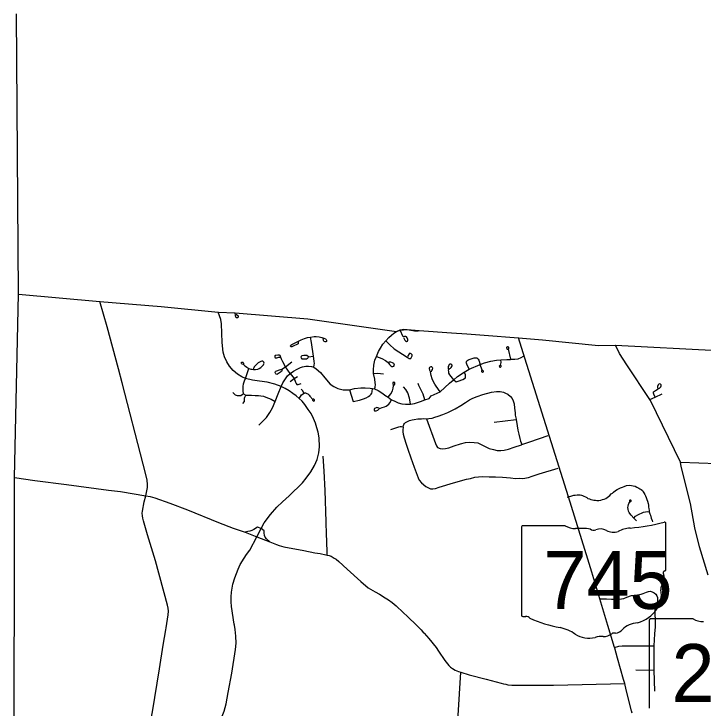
# Model space of a CAD drawing. Extents: x 1755200 to 1902939, y 644115 to 788070.
# Drawn here: x 1781021 to 1797614, y 771361 to 788070 of the extents above; entities that cross this region are included whole.
import ezdxf

# ---------------------------------------------------------------- set-up
doc = ezdxf.new("R2010")
doc.units = 0
for name, color, linetype in [('GM_X_Adjacent_County', 7, 'Continuous'), ('GM_X_City_Street', 7, 'Continuous'), ('GM_X_County', 7, 'Continuous'), ('GM_X_County_Road', 7, 'Continuous'), ('GM_X_State_Route', 7, 'Continuous'), ('GM_X_State_Shield', 7, 'Continuous')]:
    doc.layers.add(name, color=color, linetype=linetype)

msp = doc.modelspace()

# ---------------------------------------------------------------- linework, layer by layer
at = {"layer": 'GM_X_Adjacent_County'}
msp.add_line((1781136, 781321), (1781087, 788070), dxfattribs=at)
at = {"layer": 'GM_X_City_Street'}
for points in [[(1784685, 773296), (1784735, 773603), (1784745, 773698), (1784736, 773770), (1784721, 773835), (1784428, 774903), (1784235, 775534), (1784138, 775865), (1784125, 775929), (1784115, 775990), (1784111, 776055), (1784114, 776105), (1784158, 776324), (1784196, 776473), (1784235, 776672), (1784238, 776744), (1784231, 776844), (1784215, 776918), (1784131, 777234), (1783629, 779189), (1783538, 779530), (1783263, 780534), (1783093, 781151)], [(1786330, 773355), (1786325, 773382), (1786259, 773807), (1786250, 773917), (1786254, 774036), (1786263, 774150), (1786294, 774341), (1786338, 774493), (1786420, 774704), (1786472, 774820), (1786567, 774969), (1786624, 775055), (1786702, 775162), (1786871, 775480), (1786971, 775687), (1787044, 775818), (1787200, 776018), (1787355, 776199), (1787487, 776323), (1787646, 776467), (1787967, 776780), (1788061, 776896), (1788172, 777044), (1788262, 777203), (1788323, 777346), (1788361, 777509), (1788375, 777651), (1788370, 777868), (1788349, 778002), (1788313, 778109), (1788283, 778223), (1788238, 778334), (1788176, 778450), (1788109, 778552), (1788029, 778665), (1787959, 778747), (1787890, 778815), (1787816, 778881), (1787737, 778934), (1787651, 778995), (1787548, 779052), (1787457, 779100), (1787307, 779157), (1787116, 779208), (1786932, 779232), (1786764, 779254), (1786595, 779297), (1786510, 779336), (1786405, 779397), (1786303, 779486), (1786215, 779591), (1786147, 779695), (1786093, 779813), (1786060, 779930), (1786037, 780162), (1786019, 780607), (1786002, 780713), (1785941, 780892)], [(1786370, 780841), (1786422, 780806), (1786421, 780769), (1786415, 780760), (1786404, 780754), (1786381, 780755), (1786367, 780773), (1786357, 780809), (1786346, 780876)], [(1789704, 779043), (1789715, 779089), (1789724, 779146), (1789722, 779192), (1789709, 779277), (1789682, 779417), (1789680, 779501), (1789687, 779615), (1789709, 779735), (1789747, 779826), (1789795, 779948), (1789843, 780028), (1789906, 780123), (1789973, 780198), (1790046, 780282), (1790110, 780341), (1790166, 780385), (1790229, 780426), (1790323, 780455), (1790403, 780463), (1790491, 780471), (1790665, 780443), (1790696, 780441), (1790728, 780441), (1790750, 780442), (1790776, 780453)], [(1787867, 780179), (1787862, 780147), (1787861, 780131), (1787729, 780062), (1787712, 780054), (1787701, 780053), (1787689, 780060), (1787680, 780074), (1787686, 780094), (1787709, 780109), (1787748, 780129), (1787941, 780223), (1788020, 780258), (1788093, 780280), (1788164, 780289), (1788254, 780303), (1788299, 780305), (1788369, 780298), (1788433, 780283), (1788485, 780266), (1788520, 780252), (1788540, 780230), (1788546, 780218), (1788551, 780205), (1788546, 780189), (1788545, 780184), (1788532, 780177), (1788521, 780174), (1788515, 780174), (1788488, 780185), (1788482, 780196), (1788475, 780211), (1788472, 780225), (1788470, 780242), (1788474, 780262)], [(1790400, 780283), (1790418, 780247), (1790434, 780217), (1790446, 780201), (1790471, 780188), (1790486, 780189), (1790493, 780196), (1790505, 780209), (1790508, 780220), (1790508, 780235), (1790500, 780254), (1790491, 780277), (1790475, 780298), (1790458, 780306), (1790428, 780307), (1790395, 780294), (1790323, 780455)], [(1788243, 779570), (1788252, 779625), (1788258, 779657), (1788253, 779702), (1788244, 779774), (1788235, 779829), (1788185, 780159), (1788164, 780289)], [(1789973, 780198), (1790068, 780107), (1790178, 780010), (1790488, 779809), (1790541, 779778), (1790574, 779776), (1790593, 779804), (1790609, 779841), (1790609, 779864), (1790587, 779889), (1790556, 779901), (1790539, 779887), (1790496, 779823)], [(1792988, 779756), (1792931, 779997), (1792938, 780010), (1792939, 780025), (1792937, 780041), (1792932, 780051), (1792921, 780055), (1792906, 780056), (1792894, 780052), (1792888, 780049), (1792884, 780043), (1792882, 780030), (1792886, 780020), (1792890, 780010), (1792899, 780001), (1792909, 779998), (1792929, 779997)], [(1787676, 779417), (1787558, 779577), (1787492, 779693), (1787467, 779759), (1787440, 779825), (1787428, 779849), (1787417, 779859), (1787379, 779858), (1787325, 779851), (1787314, 779847), (1787304, 779836), (1787302, 779814), (1787311, 779794), (1787328, 779788), (1787348, 779789), (1787374, 779798), (1787396, 779806), (1787437, 779808)], [(1788115, 779819), (1788071, 779851), (1788053, 779851), (1787998, 779847), (1787956, 779838), (1787936, 779824), (1787933, 779811), (1787937, 779798), (1787942, 779777), (1787950, 779770), (1787962, 779766), (1787988, 779765), (1788076, 779769), (1788085, 779773), (1788097, 779787), (1788105, 779796), (1788115, 779819), (1788235, 779829)], [(1789747, 779826), (1789876, 779777), (1789971, 779727), (1790031, 779683), (1790065, 779628), (1790092, 779598), (1790118, 779583), (1790147, 779580), (1790165, 779589), (1790181, 779612), (1790179, 779637), (1790166, 779654), (1790136, 779672), (1790095, 779686), (1790047, 779691)], [(1791983, 779520), (1791922, 779641), (1791919, 779660), (1791913, 779682), (1791918, 779697), (1791924, 779721), (1791948, 779737), (1791982, 779752), (1792099, 779789), (1792137, 779795), (1792165, 779794), (1792185, 779775), (1792200, 779756), (1792211, 779733), (1792245, 779631)], [(1792997, 779757), (1793077, 779763), (1793160, 779770), (1793235, 779797), (1793288, 779833)], [(1786547, 779630), (1786518, 779638), (1786499, 779653), (1786496, 779668), (1786500, 779680), (1786505, 779688), (1786516, 779691), (1786529, 779688), (1786539, 779678), (1786545, 779666), (1786545, 779665)], [(1786545, 779665), (1786550, 779630), (1786570, 779604), (1786596, 779588), (1786626, 779566), (1786676, 779538)], [(1786680, 779535), (1786725, 779522), (1786748, 779517), (1786789, 779510), (1786835, 779509), (1786890, 779516), (1786930, 779533), (1786967, 779556), (1786998, 779588), (1787027, 779623), (1787040, 779645), (1787045, 779664), (1787040, 779685), (1787026, 779704), (1787012, 779708), (1786993, 779711), (1786964, 779705), (1786933, 779688), (1786902, 779670), (1786870, 779643), (1786850, 779626), (1786827, 779600), (1786805, 779576), (1786795, 779553), (1786784, 779519)], [(1786915, 778173), (1787099, 778353), (1787182, 778472), (1787247, 778588), (1787309, 778744), (1787382, 778923), (1787457, 779100), (1787497, 779193), (1787541, 779266), (1787610, 779355), (1787676, 779417), (1787754, 779472), (1787844, 779521), (1787920, 779561), (1787971, 779574), (1788048, 779592), (1788115, 779594), (1788185, 779581), (1788243, 779570), (1788301, 779526), (1788405, 779442), (1788510, 779307), (1788637, 779155), (1788724, 779103), (1788822, 779051), (1788950, 779024), (1789102, 779024), (1789220, 779052), (1789372, 779073), (1789476, 779073), (1789597, 779060), (1789651, 779051), (1789704, 779043), (1789793, 779002), (1789904, 778933), (1789954, 778896), (1790035, 778844), (1790115, 778777), (1790173, 778753), (1790269, 778708), (1790361, 778684), (1790451, 778673), (1790566, 778679), (1790667, 778689), (1790810, 778738), (1790917, 778780), (1791021, 778816), (1791068, 778874), (1791283, 778975), (1791509, 779180), (1791555, 779219), (1791610, 779266), (1791704, 779339), (1791865, 779449), (1791983, 779520), (1792245, 779631), (1792350, 779669), (1792502, 779709), (1792643, 779738), (1792740, 779744), (1792891, 779750), (1792976, 779755), (1792988, 779756), (1792997, 779757)], [(1787558, 779577), (1787709, 779698)], [(1791610, 779266), (1791513, 779380), (1791495, 779419), (1791490, 779457), (1791488, 779505), (1791519, 779531), (1791531, 779542), (1791546, 779561), (1791571, 779602), (1791570, 779613), (1791560, 779631), (1791545, 779639), (1791527, 779639), (1791517, 779636), (1791502, 779628), (1791490, 779609), (1791475, 779582), (1791473, 779556), (1791474, 779531), (1791486, 779505)], [(1792291, 779492), (1792282, 779485), (1792279, 779474), (1792280, 779460), (1792284, 779451), (1792306, 779443), (1792316, 779447), (1792320, 779454), (1792324, 779464), (1792324, 779473), (1792317, 779482), (1792311, 779487), (1792302, 779492), (1792291, 779492), (1792245, 779631)], [(1792739, 779614), (1792723, 779610), (1792711, 779602), (1792707, 779592), (1792709, 779577), (1792719, 779565), (1792728, 779564), (1792738, 779567), (1792747, 779576), (1792751, 779587), (1792750, 779596), (1792748, 779603), (1792739, 779614), (1792749, 779679), (1792740, 779744)], [(1786595, 779297), (1786636, 779417), (1786680, 779535)], [(1787473, 779509), (1787474, 779489), (1787469, 779476), (1787460, 779463), (1787437, 779443), (1787368, 779398), (1787351, 779394), (1787336, 779396), (1787327, 779408), (1787320, 779419), (1787313, 779435), (1787312, 779449), (1787316, 779460), (1787330, 779470), (1787350, 779478), (1787415, 779499), (1787444, 779508), (1787474, 779520), (1787558, 779577)], [(1791283, 778975), (1791186, 779107), (1791153, 779161), (1791126, 779215), (1791092, 779289), (1791069, 779364), (1791056, 779406), (1791052, 779454), (1791071, 779469), (1791085, 779490), (1791098, 779514), (1791105, 779547), (1791093, 779562), (1791080, 779574), (1791057, 779577), (1791046, 779570), (1791030, 779557), (1791018, 779545), (1791019, 779531), (1791025, 779496), (1791031, 779486), (1791050, 779454)], [(1786550, 778926), (1786543, 779001), (1786539, 779042), (1786540, 779069), (1786543, 779105), (1786552, 779162), (1786575, 779238), (1786595, 779297)], [(1787669, 779226), (1787769, 779292), (1787851, 779340)], [(1787676, 779417), (1787769, 779292), (1787797, 779210), (1787815, 779171), (1787836, 779148), (1787863, 779148), (1787891, 779156), (1787934, 779174)], [(1789682, 779417), (1789776, 779420), (1789920, 779407)], [(1791610, 779266), (1791669, 779216), (1791690, 779221), (1791717, 779229), (1791827, 779271), (1791892, 779311), (1791897, 779340), (1791893, 779389), (1791865, 779449)], [(1790035, 778844), (1790094, 778927), (1790132, 779000), (1790155, 779063), (1790161, 779120), (1790163, 779133), (1790181, 779144), (1790193, 779160), (1790196, 779177), (1790196, 779185), (1790189, 779195), (1790175, 779202), (1790161, 779203), (1790146, 779197), (1790140, 779183), (1790140, 779168), (1790156, 779135)], [(1790917, 778780), (1790877, 778915), (1790767, 779125), (1790752, 779171)], [(1796458, 778846), (1796426, 778917), (1796419, 778943), (1796418, 778975), (1796469, 779005), (1796511, 779030), (1796566, 779062), (1796593, 779090), (1796601, 779115), (1796604, 779144), (1796589, 779157), (1796569, 779165), (1796550, 779155), (1796534, 779140), (1796518, 779105), (1796519, 779073), (1796526, 779038)], [(1788004, 778943), (1787974, 778997), (1787939, 779040)], [(1789102, 779024), (1789192, 778742), (1789338, 778775), (1789440, 778805), (1789505, 778830), (1789556, 778860), (1789594, 778887), (1789624, 778916), (1789639, 778938), (1789646, 778970), (1789651, 779051)], [(1790099, 778063), (1790288, 778133), (1790322, 778136), (1790355, 778139), (1790391, 778134), (1790401, 778164), (1790408, 778184), (1790424, 778212), (1790447, 778235), (1790496, 778260), (1790542, 778283), (1790606, 778297), (1790655, 778308), (1790745, 778322), (1790833, 778326), (1790891, 778331), (1790951, 778327), (1791011, 778332), (1791088, 778342), (1791156, 778360), (1791237, 778391), (1791346, 778428), (1791465, 778477), (1791550, 778517), (1791645, 778567), (1791779, 778646), (1791891, 778716), (1791991, 778779), (1792072, 778822), (1792173, 778863), (1792314, 778908), (1792519, 778963), (1792642, 778980), (1792730, 778980), (1792809, 778966), (1792859, 778941), (1792910, 778918), (1792975, 778860), (1793014, 778811), (1793044, 778754), (1793064, 778684), (1793076, 778577), (1793087, 778469), (1793092, 778412), (1793113, 778316), (1793115, 778305), (1793141, 778155), (1793157, 778048), (1793179, 777953), (1793198, 777849), (1793216, 777788), (1793246, 777702)], [(1790566, 778679), (1790564, 778733), (1790544, 778820), (1790503, 778953), (1790458, 779032), (1790398, 779094)], [(1786293, 778954), (1786350, 778905), (1786400, 778882), (1786417, 778882), (1786455, 778882), (1786485, 778887), (1786519, 778906), (1786550, 778926)], [(1786533, 778689), (1786570, 778739), (1786571, 778794), (1786570, 778821), (1786579, 778847), (1786606, 778896)], [(1786550, 778926), (1786606, 778896), (1786629, 778890), (1786739, 778890), (1786830, 778888), (1786909, 778885), (1786967, 778876), (1787029, 778866), (1787090, 778848), (1787152, 778823), (1787212, 778796), (1787309, 778744)], [(1787890, 778815), (1787922, 778864)], [(1787922, 778864), (1787946, 778902), (1788006, 778940), (1788022, 778947), (1788045, 778946), (1788072, 778937), (1788096, 778925), (1788132, 778890), (1788148, 778869), (1788220, 778792), (1788214, 778782), (1788214, 778775), (1788218, 778768), (1788227, 778757), (1788234, 778753), (1788246, 778752), (1788258, 778760), (1788260, 778768), (1788260, 778778), (1788254, 778788), (1788242, 778796), (1788225, 778797)], [(1796333, 778788), (1796458, 778846), (1796628, 778926)], [(1789817, 778580), (1789783, 778592), (1789759, 778593), (1789727, 778583), (1789703, 778569), (1789692, 778556), (1789692, 778543), (1789695, 778531), (1789704, 778520), (1789716, 778514), (1789746, 778519), (1789785, 778534), (1789821, 778572), (1789848, 778582), (1789887, 778594), (1789941, 778609), (1789983, 778630), (1790045, 778676), (1790074, 778708), (1790115, 778777)], [(1790951, 778327), (1791171, 777731), (1791194, 777674), (1791223, 777634), (1791282, 777606), (1791336, 777599), (1791408, 777607), (1791495, 777628), (1791618, 777671), (1791771, 777721), (1791894, 777752), (1791982, 777758), (1792100, 777757), (1792190, 777743), (1792285, 777700), (1792366, 777658), (1792463, 777613), (1792568, 777582), (1792652, 777562), (1792742, 777558), (1792826, 777567), (1792929, 777595), (1793062, 777643), (1793238, 777699), (1793246, 777702), (1793442, 777768), (1793882, 777919)], [(1792584, 778243), (1793115, 778305)], [(1790391, 778134), (1790387, 778051), (1790382, 778011), (1790391, 777956), (1790414, 777867), (1790468, 777716), (1790509, 777594), (1790578, 777386), (1790658, 777159), (1790751, 776900), (1790777, 776845), (1790832, 776780), (1790937, 776695), (1791003, 776661), (1791054, 776642), (1791106, 776642), (1791170, 776649), (1791259, 776676), (1791606, 776781), (1791919, 776873), (1792011, 776891), (1792118, 776916), (1792297, 776934), (1792459, 776931), (1792613, 776927), (1792783, 776923), (1792974, 776902), (1793100, 776887), (1793202, 776892), (1793276, 776890), (1793407, 776911), (1793502, 776942), (1793667, 776996), (1794123, 777139)], [(1788551, 775488), (1788549, 775542), (1788539, 775845), (1788512, 776595), (1788492, 777063), (1788470, 777429)], [(1797070, 777278), (1797953, 777250), (1798827, 777207), (1799137, 777189), (1800084, 777145), (1801247, 777085), (1801844, 777048), (1803558, 776945), (1803593, 776944)], [(1781034, 776910), (1781525, 776843), (1782284, 776747), (1783301, 776608), (1783588, 776571), (1784196, 776473)], [(1794341, 776439), (1794370, 776448), (1794451, 776472), (1794498, 776483), (1794535, 776490), (1794578, 776494), (1794616, 776497), (1794651, 776494), (1794683, 776488), (1794712, 776477), (1794740, 776463), (1794779, 776444), (1794818, 776427), (1794842, 776409), (1794875, 776396), (1794909, 776382), (1794948, 776373), (1794981, 776365), (1795025, 776364), (1795058, 776361), (1795107, 776362), (1795149, 776364), (1795195, 776381), (1795228, 776391), (1795269, 776409), (1795306, 776427), (1795338, 776453), (1795366, 776482), (1795402, 776515), (1795430, 776533), (1795459, 776561), (1795507, 776597), (1795544, 776625), (1795575, 776640), (1795624, 776663), (1795670, 776678), (1795709, 776696), (1795771, 776719), (1795838, 776725), (1795886, 776722), (1795932, 776715), (1795976, 776701), (1796020, 776682), (1796065, 776656), (1796088, 776641), (1796124, 776622), (1796153, 776597), (1796171, 776568), (1796189, 776543), (1796207, 776505), (1796226, 776467), (1796246, 776429), (1796259, 776383), (1796277, 776343), (1796290, 776286), (1796298, 776247), (1796302, 776203), (1796308, 776160), (1796313, 776123), (1796311, 776089), (1796321, 776063), (1796331, 776039), (1796345, 776004), (1796365, 775935), (1796386, 775876), (1796399, 775845)], [(1784196, 776473), (1784304, 776457), (1784415, 776425), (1784775, 776295), (1785202, 776135), (1785945, 775831), (1786304, 775696), (1786590, 775596), (1786871, 775480), (1787181, 775362), (1787342, 775300), (1787411, 775274), (1787519, 775244), (1788001, 775154), (1788269, 775099), (1788392, 775079), (1788532, 775051)], [(1796007, 775869), (1795972, 775907), (1795944, 775934), (1795878, 776005), (1795852, 776042), (1795833, 776072), (1795820, 776102), (1795810, 776150), (1795805, 776187), (1795810, 776221), (1795817, 776259), (1795829, 776286), (1795840, 776313), (1795845, 776321), (1795860, 776324), (1795874, 776331), (1795882, 776338), (1795881, 776352), (1795879, 776360), (1795874, 776365), (1795868, 776368), (1795860, 776365), (1795852, 776365), (1795841, 776361), (1795838, 776356), (1795839, 776349), (1795842, 776339), (1795853, 776323)], [(1795944, 775934), (1795987, 775978), (1796044, 776015), (1796087, 776039), (1796128, 776052), (1796177, 776075), (1796228, 776084), (1796263, 776090), (1796311, 776089)], [(1786971, 775687), (1786883, 775714), (1786799, 775658), (1786752, 775635), (1786705, 775620), (1786653, 775610), (1786590, 775596)], [(1787181, 775362), (1787102, 775437), (1787074, 775478), (1787058, 775514), (1787047, 775581), (1787050, 775630), (1786971, 775687)], [(1788553, 775432), (1788551, 775488)], [(1788566, 775044), (1788553, 775432)], [(1788532, 775051), (1788566, 775044), (1788608, 775035), (1788660, 775017), (1788735, 774973), (1788780, 774943), (1788844, 774889), (1789044, 774708), (1789373, 774412), (1789549, 774260), (1789720, 774163), (1789825, 774100), (1789963, 774014), (1790039, 773965), (1790129, 773902), (1790224, 773825), (1790392, 773663), (1790495, 773565), (1790720, 773346), (1790822, 773244), (1790886, 773175)], [(1795129, 773990), (1795213, 773994), (1795290, 773990), (1795410, 773985), (1795490, 773982), (1795586, 773981), (1795646, 773988), (1795705, 774002), (1795780, 774029), (1795893, 774068), (1795951, 774080), (1796030, 774087), (1796079, 774093), (1796122, 774103), (1796174, 774120), (1796247, 774154), (1796297, 774168), (1796341, 774172), (1796388, 774162), (1796433, 774139), (1796473, 774101), (1796497, 774065), (1796514, 774021), (1796519, 773985), (1796515, 773940), (1796499, 773878), (1796465, 773780), (1796453, 773723), (1796450, 773664), (1796449, 773613), (1796456, 773496), (1796458, 773320), (1796444, 773152)], [(1784219, 769275), (1784630, 769643), (1785003, 769974), (1785250, 770175), (1785431, 770342), (1785586, 770486), (1785725, 770636), (1785822, 770764), (1785915, 770909), (1786003, 771088), (1786080, 771284), (1786130, 771467), (1786180, 771733), (1786271, 772205), (1786359, 772769), (1786375, 772928), (1786368, 773096), (1786350, 773256), (1786330, 773355)], [(1784617, 772879), (1784677, 773247), (1784685, 773296)], [(1790886, 773175), (1790898, 773162), (1791008, 773039), (1791186, 772817), (1791243, 772729), (1791399, 772507), (1791490, 772387), (1791532, 772349), (1791580, 772312), (1791646, 772274), (1791724, 772243), (1791780, 772223)], [(1796444, 773152), (1796429, 772857), (1796429, 772273), (1796440, 771773)], [(1784213, 769281), (1784139, 769359), (1784090, 769415), (1784062, 769474), (1784054, 769512), (1784054, 769579), (1784065, 769640), (1784254, 770715), (1784357, 771275), (1784523, 772309), (1784617, 772879)], [(1795483, 772817), (1795583, 772849), (1795668, 772859), (1795914, 772857), (1796218, 772860), (1796429, 772857)], [(1795994, 772279), (1796429, 772273)], [(1791581, 768845), (1791586, 768900), (1791605, 769182), (1791616, 769401), (1791627, 769698), (1791662, 770268), (1791678, 770556), (1791717, 771182), (1791780, 772223)], [(1792807, 771948), (1792863, 771935), (1792915, 771925), (1793012, 771917), (1793389, 771912), (1793735, 771912), (1794014, 771915), (1795728, 771954)]]:
    msp.add_lwpolyline(points, dxfattribs=at)
at = {"layer": 'GM_X_County'}
msp.add_lwpolyline([(1781021, 768152), (1781038, 774723), (1781034, 776910), (1781136, 781321), (1783093, 781151), (1784567, 781031), (1785941, 780892), (1786346, 780876), (1788100, 780727), (1790229, 780426), (1790317, 780468), (1790410, 780483), (1790491, 780471), (1790776, 780453), (1791556, 780394), (1791923, 780367), (1792339, 780337), (1793171, 780273), (1793746, 780223), (1795095, 780091), (1795507, 780094), (1797967, 779971)], dxfattribs=at)
at = {"layer": 'GM_X_County_Road'}
msp.add_lwpolyline([(1791780, 772223), (1791982, 772166), (1792387, 772058), (1792748, 771962), (1792807, 771948)], dxfattribs=at)
at = {"layer": 'GM_X_State_Route'}
for points in [[(1793373, 779630), (1793325, 779785), (1793171, 780273)], [(1797734, 774564), (1797526, 775241), (1797415, 775699), (1797309, 776284), (1797086, 777175), (1797070, 777278), (1796346, 778768), (1796333, 778788), (1795778, 779621), (1795604, 779893), (1795507, 780094)], [(1794934, 774636), (1794841, 774945), (1794370, 776448), (1793373, 779630)], [(1795323, 773347), (1795129, 773990), (1794934, 774636)], [(1795488, 772801), (1795483, 772817), (1795323, 773347)], [(1795700, 772053), (1795555, 772562), (1795488, 772801)], [(1795765, 771801), (1795728, 771954), (1795700, 772053)], [(1795905, 771243), (1795890, 771296), (1795765, 771801)]]:
    msp.add_lwpolyline(points, dxfattribs=at)
at = {"layer": 'GM_X_State_Shield'}
for p, q in [((1796719, 774697), (1796719, 775803)), ((1793238, 775714), (1793238, 773601)), ((1794292, 775750), (1793273, 775750)), ((1796718, 774698), (1796719, 774697)), ((1796318, 773474), (1796318, 771361)), ((1797372, 773511), (1796353, 773511))]:
    msp.add_line(p, q, dxfattribs=at)
for centre, major_axis, start_param, end_param in [((1795479, 778632), (3691, 0), 4.814394, 5.042369), ((1796680, 775807), (38.7, 0), 6.141152, 7.989035), ((1793278, 775719), (40.3, 0), 1.712693, 3.28349), ((1794535, 775996), (391, 0), 4.042523, 4.731795), ((1794664, 774564), (1404, 0), 1.404758, 1.657858), ((1794983, 775730), (113, 0), 3.836095, 5.185415), ((1795149, 775485), (235, 0), 0.950623, 2.079405), ((1795451, 775820), (282, 0), 4.081561, 5.145723), ((1795950, 775105), (743, 0), 1.699011, 2.107814), ((1796710, 774616), (60, 0), 1.883978, 3.671073), ((1796677, 774693), (41.5, 0), 5.05454, 6.418171), ((1796328, 774476), (360, 0), 5.934695, 6.695948), ((1796858, 774235), (262, 0), 2.387724, 3.262537), ((1795686, 774094), (923, 0), 5.101752, 6.440018), ((1793279, 773596), (40.7, 0), 3.00124, 4.508301), ((1793285, 773812), (310, 0), 4.665946, 4.897461), ((1793348, 773479), (112, 0), 0.519207, 1.627899), ((1794761, 775378), (2665, 0), 4.195997, 4.488961), ((1796358, 773479), (40.3, 0), 1.712693, 3.28349), ((1797615, 773756), (391, 0), 4.042523, 4.731795), ((1793967, 772651), (834, 0), 0.823519, 1.323587), ((1796075, 773007), (506, 0), 1.647645, 2.488434), ((1794869, 773468), (529, 0), 4.026481, 4.996735), ((1795213, 773310), (282, 0), 4.691044, 5.507374), ((1795468, 773105), (79.4, 0), 1.147584, 2.315152), ((1795434, 773396), (298, 0), 4.937069, 5.64225), ((1795175, 772738), (435, 0), 1.495662, 1.94098)]:
    msp.add_ellipse(centre, major_axis=major_axis, ratio=0.8, start_param=start_param, end_param=end_param, dxfattribs=at)

# ---------------------------------------------------------------- texts
for s, p in [('745', (1793770, 773750)), ('257', (1796854, 771510))]:
    msp.add_text(s, height=1392.2, dxfattribs=at).set_placement(p)

doc.saveas('drawing.dxf')
